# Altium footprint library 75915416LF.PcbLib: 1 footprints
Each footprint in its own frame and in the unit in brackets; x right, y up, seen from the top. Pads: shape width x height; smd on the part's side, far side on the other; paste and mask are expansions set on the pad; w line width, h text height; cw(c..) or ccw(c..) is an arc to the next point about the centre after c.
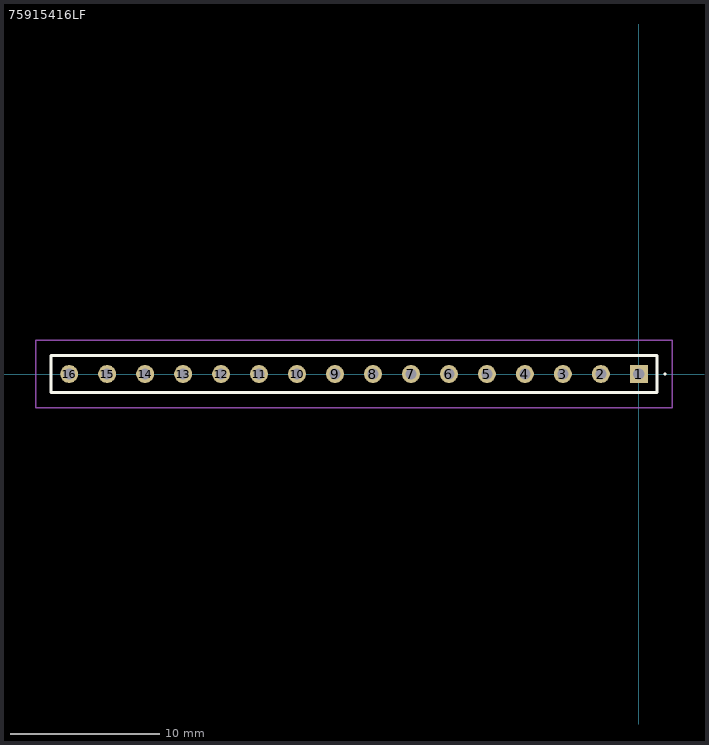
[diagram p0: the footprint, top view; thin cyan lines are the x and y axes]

## 75915416LF [mm]
pads (16):
  rect 1.2x1.2 hole 0.75: 1(0,0)
  round 1.2 hole 0.75: 2(-2.54,0) 3(-5.08,0) 4(-7.62,0) 5(-10.16,0) 6(-12.7,0) 7(-15.24,0) 8(-17.78,0) 9(-20.32,0) 10(-22.86,0) 11(-25.4,0) 12(-27.94,0) 13(-30.48,0) 14(-33.02,0) 15(-35.56,0) 16(-38.1,0)
Top Overlay:
  lines w0.1: 1.7,0 cw(c1.75,0) 1.8,0 ; 1.7,0 1.7,0 ; 1.7,0 ccw(c1.75,0) 1.8,0 ; 1.8,0 1.8,0
  lines w0.2: -39.33,-1.25 1.23,-1.25 1.23,1.25 -39.33,1.25 -39.33,-1.25
Mechanical 15:
  lines w0.1: -39.33,-1.25 1.23,-1.25 1.23,1.25 -39.33,1.25 -39.33,-1.25
Mechanical 20:
  lines w0.1: -40.33,-2.25 2.23,-2.25 2.23,2.25 -40.33,2.25 -40.33,-2.25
